// Mitsubishi GX Works2 project: 单轴运动模板（运动控制）   PLC: FX3U/FX3UC

PROGRAM MAIN
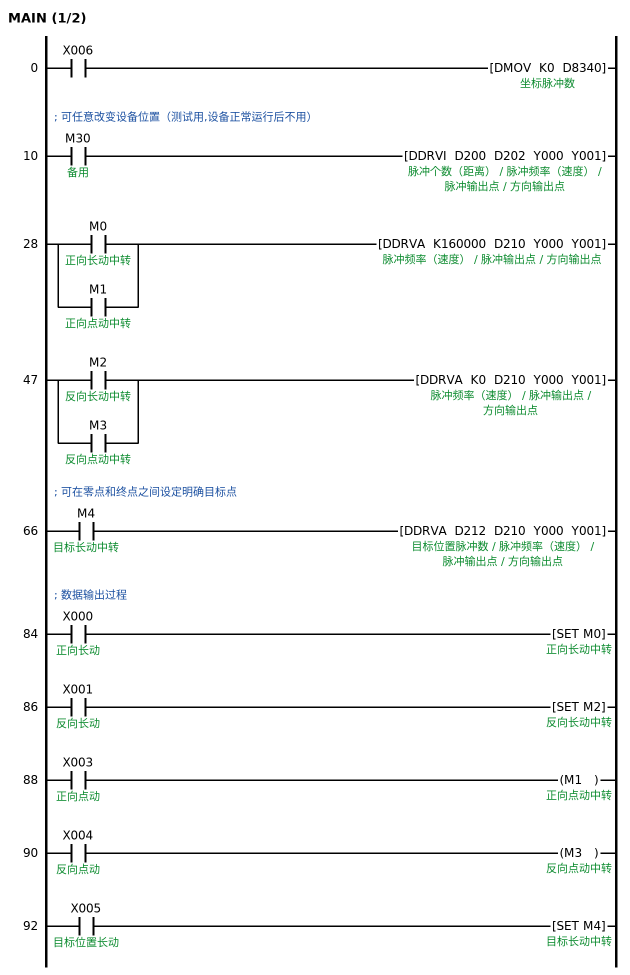
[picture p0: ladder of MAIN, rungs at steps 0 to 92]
0     LD      X006
      DMOV    K0 D8340  ; 坐标脉冲数
        [note] 设定零点
; 可任意改变设备位置（测试用,设备正常运行后不用）
10    LD      M30  ; 备用
      DDRVI   D200 D202 Y000 Y001  ; 脉冲个数（距离） / 脉冲频率（速度） / 脉冲输出点 / 方向输出点
        [note] 相对定位：可自由设定D200和D202
28    LD      M0  ; 正向长动中转
      OR      M1  ; 正向点动中转
      DDRVA   K160000 D210 Y000 Y001  ; 脉冲频率（速度）
        [note] 设备正向移动
47    LD      M2  ; 反向长动中转
      OR      M3  ; 反向点动中转
      DDRVA   K0 D210 Y000 Y001
        [note] 设备反向移动
; 可在零点和终点之间设定明确目标点
66    LD      M4  ; 目标长动中转
      DDRVA   D212 D210 Y000 Y001  ; 目标位置脉冲数
        [note] 以D212为目标点移动
; 数据输出过程
84    LD      X000  ; 正向长动
      SET     M0  ; 正向长动中转
86    LD      X001  ; 反向长动
      SET     M2  ; 反向长动中转
88    LD      X003  ; 正向点动
      OUT     M1  ; 正向点动中转
90    LD      X004  ; 反向点动
      OUT     M3  ; 反向点动中转
92    LD      X005  ; 目标位置长动
      SET     M4  ; 目标长动中转
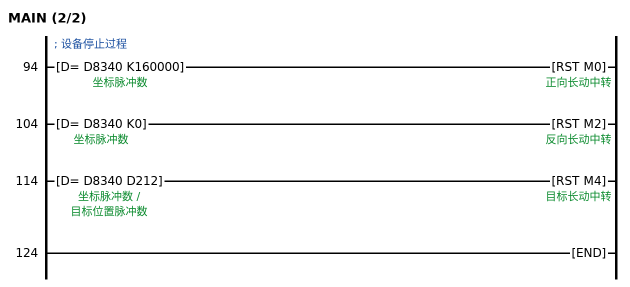
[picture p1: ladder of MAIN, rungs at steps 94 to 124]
; 设备停止过程
94    LDD=    D8340 K160000  ; 坐标脉冲数
      RST     M0  ; 正向长动中转
        [note] 设备到达终点时停住
104   LDD=    D8340 K0  ; 坐标脉冲数
      RST     M2  ; 反向长动中转
        [note] 设备返回零点时停住
114   LDD=    D8340 D212  ; 坐标脉冲数 / 目标位置脉冲数
      RST     M4  ; 目标长动中转
        [note] 设备到达目标点时停住
124   END
END_PROGRAM

// device comments not shown above
D204  ; 目标脉冲数（目标位置）
D206  ; 脉冲频率（速度）
